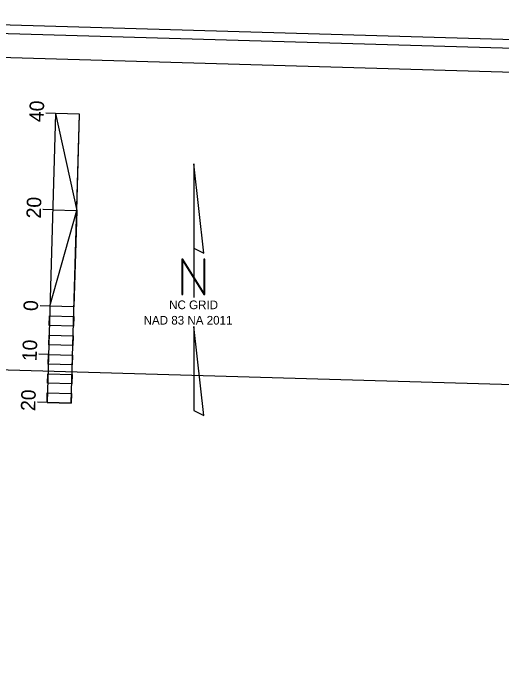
# Model space of a CAD drawing. Extents: x 2097422 to 2097881, y 685612 to 686386.
# Drawn here: x 2097527.5 to 2097628.9, y 686161.9 to 686298.2 of the extents above; entities that cross this region are included whole.
import ezdxf

# ---------------------------------------------------------------- set-up
doc = ezdxf.new("R2010")
doc.units = 0
for name, color, linetype in [('Default', 7, 'Continuous'), ('Scratch_Level_0', 7, 'Continuous'), ('Sheet Data Field CELL', 7, 'Continuous'), ('Sheet Layout Plan Border', 7, 'Continuous'), ('Sheet Plot Border Inside CELL', 7, 'Continuous'), ('Sheet Plot Border Outside CELL', 7, 'Continuous'), ('Sheet Profile CELL', 7, 'Continuous'), ('Sheet Title CELL', 7, 'Continuous')]:
    doc.layers.add(name, color=color, linetype=linetype)

msp = doc.modelspace()

# ---------------------------------------------------------------- linework, layer by layer
at = {"layer": 'Default'}
msp.add_line((2097565.04, 686240.78), (2097565.04, 686240.78), dxfattribs=at)
for points in [[(2097565, 686266.92), (2097565, 686249.45), (2097567.06, 686248.42)], [(2097562.53, 686239.8), (2097562.74, 686239.8), (2097562.74, 686246.79), (2097567.06, 686239.8), (2097567.26, 686239.8), (2097567.26, 686247.19), (2097567.06, 686247.19), (2097567.06, 686240.21), (2097562.74, 686247.19), (2097562.54, 686247.19)], [(2097565, 686215.76), (2097567.05, 686214.74), (2097565, 686233.22)]]:
    msp.add_lwpolyline(points, close=True, dxfattribs=at)
msp.add_lwpolyline([(2097565, 686249.45), (2097565, 686239.18)], dxfattribs=at)
at = {"layer": 'Scratch_Level_0'}
msp.add_lwpolyline([(2097511.35, 685744.13), (2097439.86, 685904.99), (2097448.76, 686211.16), (2097523.65, 686208.98), (2097524.1, 686224.27), (2097869.03, 686214.24), (2097857.52, 685818.41), (2097708.28, 685751.24), (2097678.12, 685684.29), (2097536.1, 685688.42)], close=True, dxfattribs=at)
at = {"layer": 'Sheet Data Field CELL'}
for p, q in [((2097536.31, 686277.39), (2097534.3, 686277.44)), ((2097535.72, 686257.39), (2097533.72, 686257.45)), ((2097534.85, 686227.41), (2097532.85, 686227.46)), ((2097534.56, 686217.41), (2097532.56, 686217.47))]:
    msp.add_line(p, q, dxfattribs=at)
at = {"layer": 'Sheet Layout Plan Border'}
msp.add_lwpolyline([(2097566.72, 685687.53), (2097536.1, 685688.42), (2097439.86, 685904.99), (2097448.76, 686211.16), (2097459.26, 686210.85), (2097523.65, 686208.98), (2097524.1, 686224.27), (2097869.03, 686214.24), (2097857.52, 685818.41)], close=True, dxfattribs=at)
at = {"layer": 'Sheet Plot Border Inside CELL'}
msp.add_lwpolyline([(2097852.7, 685617.59), (2097872.08, 686283.91), (2097450.21, 686296.17), (2097430.84, 685629.85)], close=True, dxfattribs=at)
at = {"layer": 'Sheet Plot Border Outside CELL'}
msp.add_lwpolyline([(2097861.53, 685612.13), (2097881.1, 686285.45), (2097441.29, 686298.23), (2097421.72, 685624.92)], close=True, dxfattribs=at)
at = {"layer": 'Sheet Profile CELL'}
msp.add_lwpolyline([(2097451.09, 686291.14), (2097433.65, 685691.4), (2097853.48, 685679.19), (2097870.91, 686278.94)], close=True, dxfattribs=at)
at = {"layer": 'Sheet Title CELL'}
for p, q in [((2097536.31, 686277.38), (2097534.31, 686277.44)), ((2097536.31, 686277.38), (2097534.56, 686217.41)), ((2097541.31, 686277.24), (2097536.31, 686277.38)), ((2097539.56, 686217.26), (2097541.31, 686277.24)), ((2097535.72, 686257.39), (2097533.73, 686257.45)), ((2097535.72, 686257.39), (2097540.72, 686257.24)), ((2097535.15, 686237.4), (2097533.15, 686237.46)), ((2097534.97, 686231.4), (2097539.97, 686231.25)), ((2097534.86, 686227.4), (2097532.85, 686227.46)), ((2097534.56, 686217.41), (2097532.57, 686217.46)), ((2097532.57, 686217.46), (2097532.57, 686217.46)), ((2097534.56, 686217.41), (2097539.56, 686217.26)), ((2097534.56, 686217.41), (2097534.56, 686217.41))]:
    msp.add_line(p, q, dxfattribs=at)
for points in [[(2097536.31, 686277.38), (2097540.72, 686257.24), (2097541.31, 686277.24)], [(2097535.15, 686237.4), (2097540.72, 686257.24), (2097540.15, 686237.25)], [(2097535.03, 686233.4), (2097535.08, 686235.4), (2097540.09, 686235.25), (2097540.02, 686233.25)], [(2097534.92, 686229.4), (2097534.97, 686231.4), (2097539.97, 686231.25), (2097539.91, 686229.26)], [(2097534.8, 686225.4), (2097534.86, 686227.4), (2097539.85, 686227.26), (2097539.79, 686225.26)], [(2097534.68, 686221.4), (2097534.74, 686223.4), (2097539.74, 686223.26), (2097539.68, 686221.26)], [(2097534.56, 686217.41), (2097534.62, 686219.41), (2097539.62, 686219.26), (2097539.56, 686217.26)]]:
    msp.add_lwpolyline(points, close=True, dxfattribs=at)

# ---------------------------------------------------------------- texts
at = {"layer": 'Default'}
for s, height, p in [('NC GRID', 1.797, (2097559.88, 686236.79)), ('NAD 83 NA 2011', 1.7966, (2097554.59, 686233.59))]:
    msp.add_text(s, height=height, rotation=359.9961, dxfattribs=at).set_placement(p)
at = {"layer": 'Sheet Data Field CELL'}
for s, p in [('40', (2097533.85, 686275.58)), ('20', (2097533.27, 686255.59)), ('10', (2097532.41, 686225.96)), ('20', (2097532.11, 686215.61))]:
    msp.add_text(s, height=3, rotation=88.3348, dxfattribs=at).set_placement(p)
at = {"layer": 'Sheet Title CELL'}
msp.add_text('0', height=3, rotation=88.3348, dxfattribs=at).set_placement((2097532.66, 686236.37))

doc.saveas('drawing.dxf')
